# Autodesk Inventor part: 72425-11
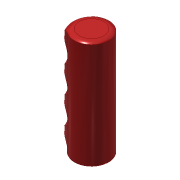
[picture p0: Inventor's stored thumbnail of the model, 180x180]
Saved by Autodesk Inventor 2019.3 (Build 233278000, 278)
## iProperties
Created: 2013-06
Part Number: 72425-11
Material: Ogólny
Document SubType Name: Modeling
Designer: CADENGINEERING4
Density: 1 g/cm^3
Appearance: Jasnoczerwona
Author: CADENGINEERING4
Revision Number: ÈÎºÎ
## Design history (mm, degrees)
feature "ÊäÈë1"
node "Bryła1"
